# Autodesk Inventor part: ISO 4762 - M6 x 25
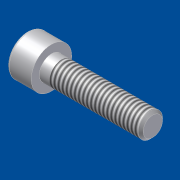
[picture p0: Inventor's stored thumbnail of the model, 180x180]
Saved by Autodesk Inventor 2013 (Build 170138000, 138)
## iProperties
Library Location: C:\Program Files\Autodesk\Inventor 6\content
Library: local
SubLibrary: ISO
Family: 13
Member: 620
Member Major Revision: 1
Member Minor Revision: 1
Comments: To add or edit properties for Autodesk Inventor files, use iProperties.
Created: 2002-10
Part Number: ISO 4762 - M6 x 25
Vendor: Autodesk Inc.
Document SubType Name: Modeling
Designer: roithn
Description: Hexagon Socket Head Cap Screw
Standard: ISO 4762 M6 x 25
Density: 1 g/cm^3
Material: Generic
Alert: To add or edit properties for Autodesk Inventor files, use iProperties.
Control State: 0
Master: False
Checked Out: False
Shininess: 64.0
Length Units: 11269
Angle Units: 11279
Time Units: 11290
Mass Units: 11283
Length Display Precision: 3
Angle Display Precision: 2
Compacted: True
EGR: 1
Density: 0.0
Volumn: 0.0
Area: 0.0
PropertySet Name: Model Information
Author: roithn
Revision Number: 1
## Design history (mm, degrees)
body "Solid1"
revolve "Revolution1" stored, may be unused: angle "d10" = 90 deg
sketch "Sketch2"
  geometry: L1 (0, -6)-(0, 8) reference; L2 (-6, 0)-(8, 0) reference; L3 (2.887, 0)-(1.443, -2.5); L4 (1.443, -2.5)-(-1.443, -2.5); L5 (-1.443, -2.5)-(-2.887, 0); L6 (-2.887, 0)-(-1.443, 2.5); L7 (-1.443, 2.5)-(1.443, 2.5); L8 (1.443, 2.5)-(2.887, 0); 2 further points
  constraints: 12 end point, 1 coincident, 1 horizontal alignment, 1 point on line, 12 other
extrude "Extrusion1" join sketch "Sketch2" stored distance "d11" = 10; taper "d12" = 0 deg
fillet "Fillet1" dims "d17" = 0.6 (= RR)
thread "Thread1" dims "d13" = 22.5 (= GEL), "d14" = 0
chamfer "Chamfer1" distance "d15" = 0.61345 (= -0.5 x SPD + 0.5 x GD); stored, may be unused: second distance "d16" = 0.61345 (= GUL), angle "d27" = 45 deg
sketch "Sketch1"
  geometry: L1 (-1.333, 0)-(25, 0); L2 (25, 0)-(25, 3); L3 (25, 3)-(2.5, 3); L4 (2.5, 3)-(1.886, 3); L5 (1.886, 3)-(0, 3); L6 (0, 3)-(0, 5); L7 (0, 5)-(-6, 5); L8 (-6, 5)-(-6, 2.887); L9 (-6, 2.887)-(-3, 2.887); L10 (-3, 2.887)-(-1.333, 0); L11 (-9.1, 0)-(34.3, 0) reference; L12 (0, -0.5)-(0, 6.5) reference; L13 (2.5, 3)-(0, 3)
  constraints: 22 end point, 6 parallel, 2 collinear, 2 perpendicular, 1 horizontal, 1 midpoint
  dimensions: "d1" = 22.5 distance from line of L3.end L2 (= GEL); "d2" = 0.61355 distance of L4.end L3.end (computed from GAL); "d3" = 6 distance between parallel lines of L8 L6 (= KOH); "d4" = 3 distance of L8.end L9.end (= INTI); "d5" = 60 deg angle of L10 L1; "d6" = 6 diameter of L3 L1 (= GD); "d7" = 6 diameter of L5 L1 (= BDM); "d8" = 5.7735 diameter of L9 L1 (= 1.1547 x SW); "d9" = 10 diameter of L7 L1 (= KOD); "d26" = 25 distance between parallel lines of L12 L2 (= NLG)
other parameters: "GD" = 6 [user parameter; used in 2 equation terms], "NLG" = 25 [user parameter; used in 1 equation term], "GEL" = 22.5 [user parameter; used in 2 equation terms], "KOD" = 10 [user parameter; used in 1 equation term], "KOH" = 6 [user parameter; used in 1 equation term], "INTI" = 3 [user parameter; used in 1 equation term], "GAL" = 0.61345 (= 0.61345 x TPU) [user parameter; used in 1 equation term], "GUL" = 0.61345 (= 0.61345 x TPU) [user parameter; used in 1 equation term], "BDM" = 6 (= NND) [user parameter; used in 1 equation term], "SW" = 5 [user parameter; used in 2 equation terms], "RR" = 0.6 [user parameter; used in 1 equation term], "SPD" = 4.7731 (= NND - 1.2269 x TPU) [user parameter; used in 1 equation term], "d18" = 0, "d19" = 0, "TOA" = 30 deg [user parameter], "PTC" = 1 (= TPU) [user parameter], "GD1" = 4.7731 (= THREADDIA - 1.2269 x TPU) [user parameter], "TPU" = 1 [user parameter; used in 5 equation terms], "THREADDIA" = 6 [user parameter; used in 1 equation term], "FAWI" = 45 deg [user parameter], "E0" = 5.775 (= 1.155 x SW) [user parameter], "NND" = 6 [user parameter; used in 2 equation terms]
